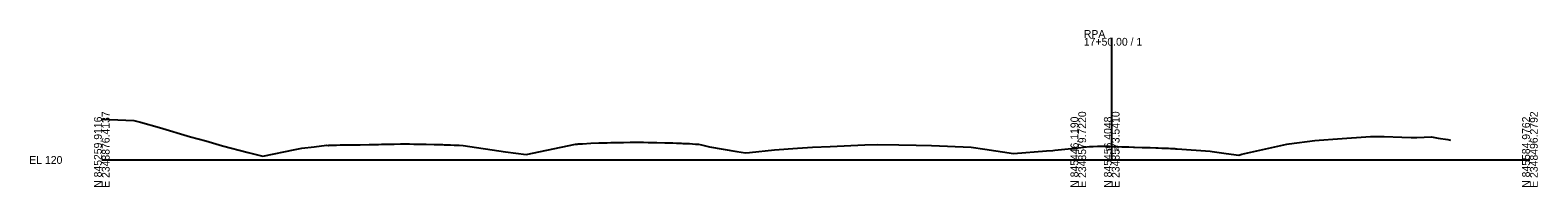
# Model space of a CAD drawing. Extents: x -76 to 2348158, y -10 to 845166.
# Drawn here: x 1224 to 1765, y 6990 to 7047 of the extents above; entities that cross this region are included whole.
import ezdxf

# ---------------------------------------------------------------- set-up
doc = ezdxf.new("R2010")
doc.units = 0
for name, color, linetype in [('Default', 7, 'Continuous'), ('Exist Cross Section Cell', 7, 'Continuous'), ('Exist XS Center Line Elevation Label', 7, 'Continuous'), ('Exist XS Ground Line', 7, 'Continuous')]:
    doc.layers.add(name, color=color, linetype=linetype)

msp = doc.modelspace()

# ---------------------------------------------------------------- linework, layer by layer
at = {"layer": 'Exist Cross Section Cell'}
for p, q in [((1612.28, 7000), (1612.28, 7043.91)), ((1250, 7000), (1600.28, 7000)), ((1600.28, 7000), (1612.28, 7000)), ((1612.28, 7000), (1762.28, 7000))]:
    msp.add_line(p, q, dxfattribs=at)
at = {"layer": 'Exist XS Ground Line'}
msp.add_lwpolyline([(1250, 7014.64), (1261.53, 7014.14), (1263.85, 7013.59), (1270.71, 7011.65), (1281.84, 7008.36), (1287.37, 7006.84), (1293.31, 7005.07), (1302.56, 7002.64), (1307.82, 7001.38), (1319.35, 7003.75), (1321.74, 7004.24), (1326.19, 7004.78), (1330.63, 7005.29), (1331.15, 7005.26), (1331.46, 7005.27), (1334.14, 7005.36), (1335.55, 7005.39), (1336.14, 7005.4), (1336.83, 7005.41), (1338.37, 7005.42), (1339.77, 7005.44), (1340.84, 7005.45), (1342.69, 7005.47), (1345.86, 7005.52), (1346.76, 7005.55), (1347.43, 7005.57), (1348.62, 7005.6), (1349.25, 7005.62), (1350.31, 7005.65), (1351.6, 7005.68), (1353.81, 7005.72), (1354.49, 7005.73), (1354.89, 7005.74), (1357.13, 7005.78), (1357.73, 7005.77), (1359.6, 7005.76), (1360.41, 7005.76), (1361.88, 7005.74), (1363.34, 7005.72), (1363.74, 7005.71), (1364.35, 7005.7), (1365.55, 7005.67), (1366.31, 7005.65), (1369.26, 7005.59), (1370.07, 7005.57), (1371.49, 7005.53), (1372.18, 7005.51), (1372.76, 7005.5), (1373.72, 7005.46), (1374.6, 7005.43), (1375.13, 7005.41), (1376.41, 7005.35), (1378.23, 7005.28), (1379.61, 7005.21), (1394.84, 7002.96), (1402.23, 7001.91), (1409.6, 7003.5), (1419.96, 7005.71), (1420.5, 7005.74), (1420.88, 7005.77), (1421.78, 7005.81), (1422.38, 7005.84), (1425.46, 7005.99), (1428.33, 7006.11), (1429.64, 7006.17), (1430, 7006.18), (1430.75, 7006.21), (1431.24, 7006.22), (1432.63, 7006.25), (1434.43, 7006.29), (1434.81, 7006.3), (1436.28, 7006.33), (1437.17, 7006.34), (1439.58, 7006.38), (1440.21, 7006.38), (1441.91, 7006.39), (1443.03, 7006.39), (1444.28, 7006.37), (1445.99, 7006.33), (1447.12, 7006.31), (1449.12, 7006.27), (1451.95, 7006.21), (1453.39, 7006.17), (1453.82, 7006.16), (1454.33, 7006.13), (1454.83, 7006.12), (1456.19, 7006.08), (1457.85, 7006.01), (1458.47, 7005.98), (1460.79, 7005.87), (1462.95, 7005.74), (1463.33, 7005.71), (1464, 7005.71), (1465.08, 7005.47), (1467.98, 7004.78), (1477.76, 7003.07), (1480.88, 7002.51), (1482.4, 7002.7), (1491.35, 7003.7), (1499.53, 7004.25), (1504.97, 7004.6), (1511.29, 7004.84), (1523.71, 7005.43), (1528.37, 7005.53), (1535.91, 7005.41), (1542.08, 7005.35), (1547.62, 7005.21), (1561.8, 7004.64), (1566.72, 7003.87), (1577.07, 7002.33), (1588.93, 7003.27), (1591.13, 7003.45), (1591.89, 7003.53), (1600.28, 7004.39), (1604.3, 7004.82), (1605, 7004.84), (1605.66, 7004.87), (1607.17, 7004.97), (1607.49, 7004.99), (1608.67, 7004.99), (1610.41, 7004.94), (1611.48, 7004.91), (1612.28, 7004.89), (1613.51, 7004.86), (1614.07, 7004.84), (1614.41, 7004.83), (1615.91, 7004.78), (1617.31, 7004.73), (1618.44, 7004.69), (1620.08, 7004.63), (1620.48, 7004.62), (1623.2, 7004.54), (1625.01, 7004.48), (1626.03, 7004.45), (1628.06, 7004.38), (1628.91, 7004.34), (1630.29, 7004.29), (1631.85, 7004.24), (1632.23, 7004.22), (1632.68, 7004.21), (1633.37, 7004.17), (1634.07, 7004.14), (1634.38, 7004.12), (1634.93, 7004.08), (1635.24, 7004.05), (1635.75, 7004.05), (1647.63, 7003.12), (1648.28, 7003.07), (1653.36, 7002.36), (1657.87, 7001.74), (1659, 7002.03), (1675.03, 7005.67), (1675.94, 7005.84), (1685.1, 7006.98), (1686.72, 7007.14), (1693.23, 7007.58), (1705.09, 7008.48), (1710.03, 7008.46), (1716.29, 7008.2), (1719.67, 7008.05), (1721.7, 7008.1), (1726.96, 7008.29), (1729.42, 7007.8), (1732.81, 7007.42), (1733.82, 7007.1)], dxfattribs=at)

# ---------------------------------------------------------------- texts
at = {"layer": 'Default'}
msp.add_text('-', height=0.0001, dxfattribs=at).set_placement((1250, 7000))
at = {"layer": 'Exist Cross Section Cell'}
for s, p in [('17+50.00 / 1', (1602.28, 7041.11)), ('RPA', (1602.28, 7043.91)), ('EL 120', (1224, 6998.6))]:
    msp.add_text(s, height=2.8, dxfattribs=at).set_placement(p)
for s, p in [('N 845259.9116', (1250, 6990)), ('E 2348876.4137', (1252.8, 6990)), ('N 845446.1190', (1600.28, 6990)), ('E 2348579.7220', (1603.08, 6990)), ('N 845456.4048', (1612.28, 6990)), ('E 2348573.5410', (1615.08, 6990)), ('N 845584.9762', (1762.28, 6990)), ('E 2348496.2792', (1765.08, 6990))]:
    msp.add_text(s, height=2.8, rotation=90, dxfattribs=at).set_placement(p)
at = {"layer": 'Exist XS Center Line Elevation Label'}
msp.add_text('124.89', height=1.2, dxfattribs=at).set_placement((1609.84, 7003.29))

doc.saveas('drawing.dxf')
